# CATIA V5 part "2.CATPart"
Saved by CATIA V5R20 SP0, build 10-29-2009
Part number: 2
Bounding box of the stored display mesh (mm): x -10 to 10, y -14.992 to 14.992, z -15 to 159.99
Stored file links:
  E:\Ehsan\Amoozesh\CATIA\CATIA Course\Advanced\Exercises\DMU Kinematic\11\2.CATPart
  E:\Ehsan\Amoozesh\CATIA\CATIA Course\Advanced\Exercises\DMU Kinematic\11\Product1.CATProduct
  E:\Ehsan\Amoozesh\CATIA\CATIA Course\Advanced\Exercises\DMU Kinematic\11\4.CATPart
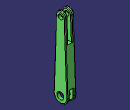
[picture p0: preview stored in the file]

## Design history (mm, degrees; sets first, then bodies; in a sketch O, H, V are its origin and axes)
Body1 (main body)
  Sketch1 on yz-plane, origin (0, 0, 0), H (0, 1, 0), V (0, 0, 1)
    circle A1 centre (0, 0) radius 7.5
    construction line L1 (0, 0) -> (0, 150)
    line L2 (-14.9917, 0.5) -> (-9.9944, 150.3333)
    line L3 (9.9944, 150.3333) -> (14.9917, 0.5)
    arc A2 centre (0, 150) radius 10 from (-9.9944, 150.3333) to (9.9944, 150.3333) cw
    arc A3 centre (0, 0) radius 15 from (14.9917, 0.5) to (-14.9917, 0.5) cw
    circle A4 centre (0, 150) radius 5
    radius A1 = 7.5
    radius A3 = 15
    radius A2 = 10
    length L1 = 150
    radius A4 = 5
    vertical: L1 V
    tangency: A2 L2, A3 L2, A2 L3, A3 L3
  Pad1: profile Sketch1, direction (1, 0, 0), length 10, mirrored extent
  Sketch2 on zx-plane, origin (0, 0, 0), H (-1, 0, 0), V (0, 0, 1)
    line L1 (-4, 160) -> (4, 160)
    line L2 (4, 160) -> (4, 100)
    line L3 (4, 100) -> (-4, 100)
    line L4 (-4, 100) -> (-4, 160)
    reference projected line E1 (10, 160) -> (-10, 160) from face of Pad1 from Sketch1.A2
    distance L2 L4 = 8
    length L4 = 60
    horizontal: L1 H, L3 H
    vertical: L2 V, L4 V
    coincidence: L1 E1
    symmetry: L2 L4 V
  Pocket1: profile Sketch2, direction (0, -1, 0), through (limit type 6), opposite side through (limit type 6)
  Sketch3 on zx-plane, origin (0, 0, 0), H (-1, 0, 0), V (0, 0, 1)
    line L1 (-4, 15) -> (4, 15)
    line L2 (4, 15) -> (4, -15)
    line L3 (4, -15) -> (-4, -15)
    line L4 (-4, -15) -> (-4, 15)
    reference projected line E1 (10, -15) -> (-10, -15) from face of Pad1 from Sketch1.A3
    length L2 = 30
    length L3 = 8
    horizontal: L1 H, L3 H
    vertical: L2 V, L4 V
    symmetry: L2 L4 V
    coincidence: L3 E1
  Pocket2: profile Sketch3, direction (0, -1, 0), through (limit type 6), opposite side through (limit type 6)
  Fillet1: radius 1.5, on edge [start face of Pad1 | face of Pad1 from Sketch1.L2]; edge [face of Pad1 from Sketch1.L2 | end face of Pad1]; edge [face of Pad1 from Sketch1.L2 | face of Pocket1 from Sketch2.L4]; edge [face of Pocket1 from Sketch2.L2 | face of Pad1 from Sketch1.L2]; edge [face of Pad1 from Sketch1.A3 | face of Pocket2 from Sketch3.L2]; edge [face of Pad1 from Sketch1.A3 | face of Pocket2 from Sketch3.L4]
